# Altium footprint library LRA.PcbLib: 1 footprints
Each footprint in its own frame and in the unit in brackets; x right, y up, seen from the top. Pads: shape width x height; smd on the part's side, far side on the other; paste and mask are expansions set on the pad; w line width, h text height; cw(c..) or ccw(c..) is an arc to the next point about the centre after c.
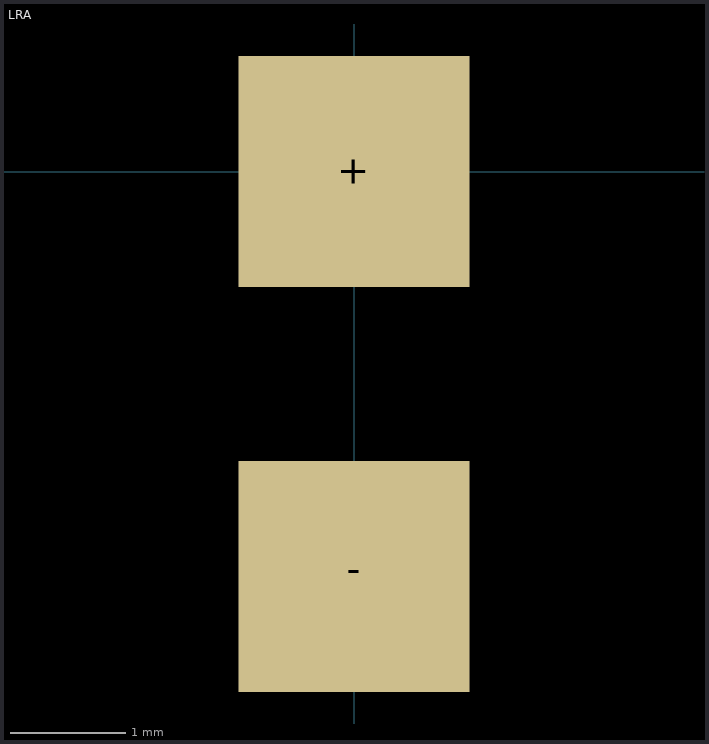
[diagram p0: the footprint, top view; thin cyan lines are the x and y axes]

## LRA [mm] "LRA Actuator"
pads (2):
  rect 2x2 smd: +(0,0) -(0,-3.5)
